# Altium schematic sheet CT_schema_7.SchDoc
size 308 x 210 mm
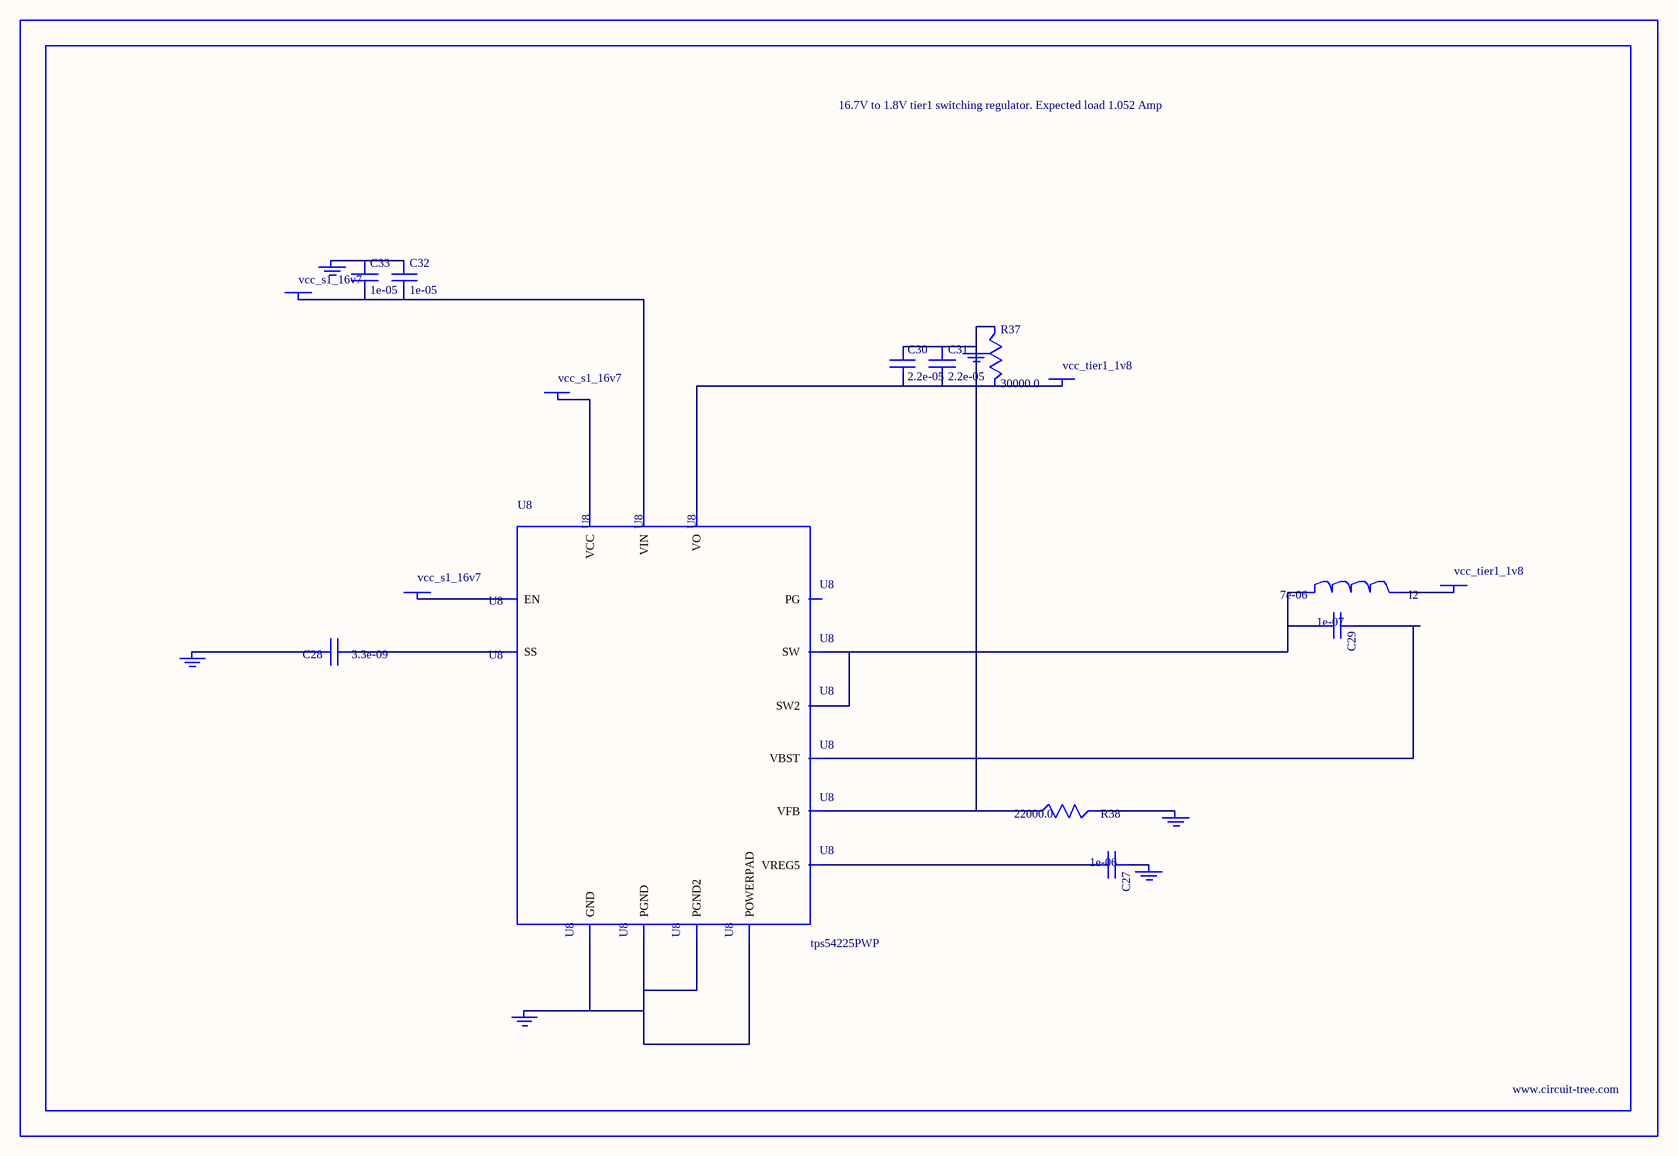
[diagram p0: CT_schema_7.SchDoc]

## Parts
BORDER6  (no value)
C27  1e-06  [C0603]
C28  3.3e-09  [C0402]
C29  1e-07  [C0402]
C30  2.2e-05  [C1210]
C31  2.2e-05  [C1210]
C32  1e-05  [C1210]
C33  1e-05  [C1210]
GND_INSTANCE_6_0  (no value)
GND_INSTANCE_6_1  (no value)
GND_INSTANCE_6_2  (no value)
GND_INSTANCE_6_3  (no value)
GND_INSTANCE_6_4  (no value)
GND_INSTANCE_6_5  (no value)
I2  7e-06  [DR1040]
POWER_INSTANCE_6_0  vcc_tier1_1v8
POWER_INSTANCE_6_1  vcc_s1_16v7
POWER_INSTANCE_6_2  vcc_tier1_1v8
POWER_INSTANCE_6_3  vcc_s1_16v7
POWER_INSTANCE_6_4  vcc_s1_16v7
R37  30000.0  [R0603]
R38  22000.0  [R0603]
U8  tps54225PWP  [HTSSOP14]

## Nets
NetC27_1: C27.1 GND_INSTANCE_6_2.0(GND)
NetC27_2: C27.2 U8.3(VREG5)
NetC28_1: C28.1 U8.4(SS)
NetC28_2: C28.2 GND_INSTANCE_6_3.0(GND)
NetC29_1: C29.1 U8.12(VBST)
NetC29_2: C29.2 I2.1 U8.10(SW) U8.11(SW2)
NetC30_1: C30.1 C31.1 GND_INSTANCE_6_0.0(GND) R37.1 R38.1 U8.2(VFB)
NetC30_2: C30.2 C31.2 POWER_INSTANCE_6_0.0(PWR) R37.2 U8.1(VO)
NetC32_1: C32.1 C33.1 GND_INSTANCE_6_5.0(GND)
NetC32_2: C32.2 C33.2 POWER_INSTANCE_6_3.0(PWR) U8.13(VIN)
NetGND_INSTANCE_6_1_0: GND_INSTANCE_6_1.0(GND) R38.2
NetGND_INSTANCE_6_4_0: GND_INSTANCE_6_4.0(GND) U8.5(GND) U8.8(PGND) U8.9(PGND2) U8.15(POWERPAD)
NetI2_2: I2.2 POWER_INSTANCE_6_2.0(PWR)
NetPOWER_INSTANCE_6_1_0: POWER_INSTANCE_6_1.0(PWR) U8.7(EN)
NetPOWER_INSTANCE_6_4_0: POWER_INSTANCE_6_4.0(PWR) U8.14(VCC)

Not connected (* = marked no-connect by the designer): U8 6(PG)

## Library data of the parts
BORDER6 = BORDER_PAGE6
C27 = C0603C105K3RACTU
C28 = C0402C332K3RAC
C29 = C0402C104K3RACTU
C30 C31 = GRM32ER61E226ME15L
C32 C33 = C1210C106K5PACTU
GND_INSTANCE_6_0-GND_INSTANCE_6_5 = GND
I2 = DR1040-7R0-R
POWER_INSTANCE_6_0-POWER_INSTANCE_6_4 = PWR
R37 = RC0603JR-0730KL
R38 = RC0603JR-0722KL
